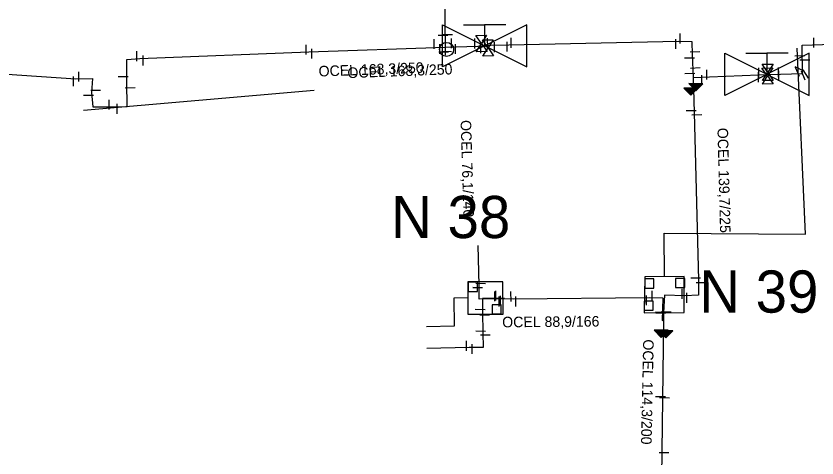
# Model space of a CAD drawing. Extents: x -642943 to -623314, y -1138561 to -1113539.
# Drawn here: x -641799.7 to -641742.7, y -1115261.5 to -1115230.1 of the extents above; entities that cross this region are included whole.
import ezdxf

# ---------------------------------------------------------------- set-up
doc = ezdxf.new("R2010")
doc.units = 0
for name, color, linetype in [('horkovod armatury', 7, 'Continuous'), ('horkovod dimenze', 7, 'Continuous'), ('horkovod předisol', 7, 'Continuous'), ('horkovod sváry', 7, 'Continuous'), ('horkovod trasa', 7, 'Continuous'), ('horkovod zrušený', 7, 'Continuous'), ('horkovod číslo šachty', 7, 'Continuous'), ('horkovod šachty', 7, 'Continuous')]:
    doc.layers.add(name, color=color, linetype=linetype)

# ---------------------------------------------------------------- blocks, each defined once
blk = doc.blocks.new('SPH')
at = {"layer": 'horkovod sváry'}
blk.add_line((0, -0.035), (0, 0.035), dxfattribs=at)
blk = doc.blocks.new('SPH_1')
at = {"layer": 'horkovod sváry'}
blk.add_line((0.0001, -0.035), (-0.0001, 0.035), dxfattribs=at)
blk = doc.blocks.new('SPH_2')
at = {"layer": 'horkovod sváry'}
blk.add_line((-0.0001, -0.0349), (0.0001, 0.0349), dxfattribs=at)
blk = doc.blocks.new('POINT_DISPLAY')
blk.add_line((0, 0), (0, 0))
blk = doc.blocks.new('SH')
at = {"layer": 'horkovod armatury'}
for p, q in [((-0.0568, -0.0385), (-0.0564, 0.0379)), ((-0.0564, 0.0379), (0, 0)), ((0.0007, -0.0004), (0.0582, 0.0375)), ((0.0582, 0.0375), (0.0581, -0.0389)), ((0.0007, -0.0004), (-0.0568, -0.0385)), ((0.0581, -0.0389), (0.0007, -0.0004))]:
    blk.add_line(p, q, dxfattribs=at)
blk = doc.blocks.new('6.46')
at = {"layer": 'horkovod armatury'}
for p, q in [((0, 0.0467), (0.0034, 0.0467)), ((0, 0.0397), (0.0105, 0.0397)), ((0, 0.0327), (0.0177, 0.0327)), ((0, 0.0257), (0.0249, 0.0257)), ((0, 0.0187), (0.032, 0.0187)), ((0, 0.0117), (0.0392, 0.0117)), ((0, 0.0047), (0.0463, 0.0047)), ((0, -0.0023), (0.0488, -0.0023)), ((0, -0.0093), (0.0416, -0.0093)), ((0, -0.0163), (0.0345, -0.0163)), ((0, -0.0233), (0.0273, -0.0233)), ((0, -0.0303), (0.0202, -0.0303)), ((0, -0.0373), (0.013, -0.0373)), ((0, -0.0443), (0.0058, -0.0443))]:
    blk.add_line(p, q, dxfattribs=at)
blk.add_lwpolyline([(0, 0.05), (0, -0.05), (0.0512, 0)], close=True, dxfattribs=at)
blk = doc.blocks.new('SCH_01_10')
at = {"layer": 'horkovod armatury'}
for p, q in [((10, 5), (-10, -5)), ((-10, -5), (-10, 5)), ((-10, 5), (10, -5)), ((-5, 5), (0, 5)), ((0, 5), (0, 0)), ((5, 5), (0, 5)), ((10, -5), (10, 5))]:
    blk.add_line(p, q, dxfattribs=at)

msp = doc.modelspace()

# ---------------------------------------------------------------- linework, layer by layer
at = {"layer": 'horkovod předisol'}
msp.add_line((-641753.655, -1115251.788), (-641753.821, -1115263.96), dxfattribs=at)
for points in [[(-641758.697, -1115223.753), (-641762.335, -1115224.239), (-641769.279, -1115224.732), (-641769.182, -1115232.315)], [(-641751.554, -1115234.469), (-641746.89, -1115234.261), (-641743.761, -1115234.175), (-641743.786, -1115232.164), (-641739.432, -1115232.02), (-641702.421, -1115231.343), (-641702.298, -1115235.396), (-641702.102, -1115236.408), (-641701.237, -1115236.398), (-641688.715, -1115235.999), (-641688.871, -1115231.268), (-641683.013, -1115231.141), (-641670.373, -1115230.715)], [(-641769.182, -1115232.315), (-641766.857, -1115232.233), (-641765.941, -1115232.175), (-641764.652, -1115232.13), (-641752.604, -1115231.888), (-641751.641, -1115231.908), (-641751.606, -1115232.847), (-641751.554, -1115234.469)], [(-641807.004, -1115233.78), (-641795.449, -1115234.548), (-641794.27, -1115234.54), (-641794.336, -1115235.525), (-641794.239, -1115236.552), (-641792.768, -1115236.552), (-641791.81, -1115236.529), (-641791.828, -1115234.784), (-641791.823, -1115233.171), (-641790.889, -1115233.104), (-641778.885, -1115232.64), (-641769.182, -1115232.315)], [(-641769.182, -1115232.315), (-641769.175, -1115232.867)], [(-641751.554, -1115234.469), (-641751.522, -1115235.262), (-641751.478, -1115236.959), (-641751.167, -1115248.877), (-641751.154, -1115249.933), (-641752.138, -1115249.977), (-641753.585, -1115249.94), (-641753.646, -1115251.168), (-641753.655, -1115251.788)], [(-641764.977, -1115250.198), (-641766.758, -1115250.223), (-641766.763, -1115249.228), (-641766.838, -1115246.394)], [(-641764.977, -1115250.198), (-641764.977, -1115250.159), (-641766.535, -1115250.179), (-641766.522, -1115251.143), (-641766.493, -1115252.615), (-641766.473, -1115253.646), (-641767.47, -1115253.656), (-641770.481, -1115253.733)], [(-641753.655, -1115251.788), (-641753.727, -1115251.738), (-641753.682, -1115250.15), (-641754.661, -1115250.123), (-641764.343, -1115250.209), (-641764.977, -1115250.198)]]:
    msp.add_lwpolyline(points, dxfattribs=at)
at = {"layer": 'horkovod trasa'}
msp.add_line((-641753.655, -1115251.788), (-641753.821, -1115263.96), dxfattribs=at)
for points in [[(-641758.697, -1115223.753), (-641762.335, -1115224.239), (-641769.279, -1115224.732), (-641769.182, -1115232.315)], [(-641751.554, -1115234.469), (-641746.89, -1115234.261), (-641743.761, -1115234.175), (-641743.786, -1115232.164), (-641739.432, -1115232.02), (-641702.421, -1115231.343), (-641702.298, -1115235.396), (-641702.102, -1115236.408), (-641701.237, -1115236.398), (-641688.715, -1115235.999), (-641688.871, -1115231.268), (-641683.013, -1115231.141), (-641670.373, -1115230.715)], [(-641769.182, -1115232.315), (-641766.857, -1115232.233), (-641765.941, -1115232.175), (-641764.652, -1115232.13), (-641752.604, -1115231.888), (-641751.641, -1115231.908), (-641751.606, -1115232.847), (-641751.554, -1115234.469)], [(-641807.004, -1115233.78), (-641795.449, -1115234.548), (-641794.27, -1115234.54), (-641794.336, -1115235.525), (-641794.239, -1115236.552), (-641792.768, -1115236.552), (-641791.81, -1115236.529), (-641791.828, -1115234.784), (-641791.823, -1115233.171), (-641790.889, -1115233.104), (-641778.885, -1115232.64), (-641769.182, -1115232.315)], [(-641769.182, -1115232.315), (-641769.175, -1115232.867)], [(-641751.554, -1115234.469), (-641751.522, -1115235.262), (-641751.478, -1115236.959), (-641751.167, -1115248.877), (-641751.154, -1115249.933), (-641752.138, -1115249.977), (-641753.585, -1115249.94), (-641753.646, -1115251.168), (-641753.655, -1115251.788)], [(-641764.977, -1115250.198), (-641766.758, -1115250.223), (-641766.763, -1115249.228), (-641766.838, -1115246.394)], [(-641764.977, -1115250.198), (-641764.977, -1115250.159), (-641766.535, -1115250.179), (-641766.522, -1115251.143), (-641766.493, -1115252.615), (-641766.473, -1115253.646), (-641767.47, -1115253.656), (-641770.481, -1115253.733)], [(-641753.655, -1115251.788), (-641753.727, -1115251.738), (-641753.682, -1115250.15), (-641754.661, -1115250.123), (-641764.343, -1115250.209), (-641764.977, -1115250.198)]]:
    msp.add_lwpolyline(points, dxfattribs=at)
at = {"layer": 'horkovod zrušený'}
for p, q in [((-641743.544, -1115245.588), (-641744.154, -1115232.385)), ((-641778.508, -1115235.381), (-641794.902, -1115236.798)), ((-641753.582, -1115248.63), (-641753.597, -1115245.516)), ((-641753.597, -1115245.516), (-641743.544, -1115245.588)), ((-641767.566, -1115250.135), (-641768.57, -1115250.139)), ((-641768.57, -1115250.139), (-641768.553, -1115252.135)), ((-641768.553, -1115252.135), (-641770.508, -1115252.187))]:
    msp.add_line(p, q, dxfattribs=at)
at = {"layer": 'horkovod šachty'}
for p, q in [((-641767.539, -1115249.02), (-641767.539, -1115249.67)), ((-641766.889, -1115249.02), (-641767.539, -1115249.02)), ((-641766.889, -1115249.67), (-641766.889, -1115249.02)), ((-641754.989, -1115248.78), (-641754.989, -1115249.43)), ((-641754.339, -1115248.78), (-641754.989, -1115248.78)), ((-641754.339, -1115249.43), (-641754.339, -1115248.78)), ((-641752.799, -1115248.75), (-641752.799, -1115249.4)), ((-641752.149, -1115248.75), (-641752.799, -1115248.75)), ((-641752.149, -1115249.4), (-641752.149, -1115248.75)), ((-641767.539, -1115249.67), (-641766.889, -1115249.67)), ((-641754.989, -1115249.43), (-641754.339, -1115249.43)), ((-641752.799, -1115249.4), (-641752.149, -1115249.4)), ((-641755.029, -1115250.36), (-641755.029, -1115251.01)), ((-641754.379, -1115250.36), (-641755.029, -1115250.36)), ((-641754.379, -1115251.01), (-641754.379, -1115250.36)), ((-641765.839, -1115250.62), (-641765.839, -1115251.27)), ((-641765.189, -1115250.62), (-641765.839, -1115250.62)), ((-641765.189, -1115251.27), (-641765.189, -1115250.62)), ((-641765.839, -1115251.27), (-641765.189, -1115251.27)), ((-641755.029, -1115251.01), (-641754.379, -1115251.01))]:
    msp.add_line(p, q, dxfattribs=at)
for points in [[(-641752.179, -1115251.169), (-641752.184, -1115248.619), (-641754.984, -1115248.638), (-641755.018, -1115251.188), (-641752.179, -1115251.169)], [(-641765.066, -1115251.279), (-641765.072, -1115248.979), (-641767.572, -1115248.985), (-641767.566, -1115251.285), (-641765.066, -1115251.279)]]:
    msp.add_lwpolyline(points, dxfattribs=at)
msp.add_circle((-641769.083, -1115232.463), 0.5, dxfattribs=at)

# ---------------------------------------------------------------- block references
at = {"layer": 'horkovod armatury', "xscale": 0.2999795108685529, "yscale": 0.2999795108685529}
for p in [(-641766.374, -1115232.213), (-641746.297, -1115234.236)]:
    msp.add_blockref('SCH_01_10', p, dxfattribs=at)
at = {"layer": 'horkovod armatury'}
for name, p, xscale, yscale, rotation in [('SH', (-641766.598, -1115232.038), 9.999984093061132, 9.99998409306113, -88.00122409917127), ('SH', (-641766.128, -1115232.348), 9.999988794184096, 9.999988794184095, -89.04612800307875), ('SH', (-641746.248, -1115234.348), 9.999994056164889, 9.999994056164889, -87.88081933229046), ('SH', (-641746.238, -1115234.088), 10.000020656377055, 10.000020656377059, -89.52294863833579), ('6.46', (-641751.36, -1115234.9), 9.999978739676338, 9.99997873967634, -90.41168409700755), ('6.46', (-641751.71, -1115235.21), 10, 10, -90.00000000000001), ('6.46', (-641753.82, -1115252.42), 10.000008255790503, 10.000008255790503, -90.58457879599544), ('6.46', (-641753.48, -1115252.46), 10.000008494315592, 10.00000849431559, -91.00723883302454)]:
    msp.add_blockref(name, p, dxfattribs=dict(at, xscale=xscale, yscale=yscale, rotation=rotation))
at = {"layer": 'horkovod sváry'}
for name, p, xscale, yscale, rotation in [('SPH_2', (-641769.34, -1115231.472), 10.000011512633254, 10.000011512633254, 90.92932050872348), ('SPH_2', (-641769.01, -1115231.432), 10.000016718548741, 10.000016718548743, 89.79616110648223), ('SPH_2', (-641769.291, -1115232.64), 9.999997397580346, 9.999997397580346, -91.19804079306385), ('SPH', (-641769.288, -1115232.64), 9.999997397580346, 9.999997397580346, -91.19804079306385), ('SPH_2', (-641769.288, -1115232.64), 9.999997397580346, 9.999997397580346, -91.19804079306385), ('SPH', (-641769.078, -1115232.6), 9.999993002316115, 9.999993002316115, -91.31839937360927), ('SPH', (-641751.42, -1115232.63), 10.000014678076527, 10.000014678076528, -88.46248895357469), ('SPH', (-641751.8, -1115233.07), 9.99998074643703, 9.999980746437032, -89.28787850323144), ('SPH_2', (-641743.96, -1115232.931), 9.999986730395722, 9.99998673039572, 91.14280189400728), ('SPH_2', (-641743.6, -1115233.201), 10.000019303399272, 10.00001930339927, -89.67689839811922), ('SPH_1', (-641751.39, -1115233.77), 9.999996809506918, 9.999996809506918, -86.47221275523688), ('SPH_1', (-641743.99, -1115233.86), 9.99999407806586, 9.99999407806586, 62.764839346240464), ('SPH', (-641744.12, -1115234.07), 9.999997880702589, 9.999997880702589, 25.2680652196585), ('SPH', (-641792.08, -1115234.39), 9.999998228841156, 9.999998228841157, -90.78122855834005), ('SPH_1', (-641751.78, -1115234.16), 9.999983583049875, 9.999983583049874, -88.24574883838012), ('SPH_1', (-641743.7, -1115234.33), 10.000006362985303, 10.000006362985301, 21.91080350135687), ('SPH', (-641743.54, -1115234.21), 10.00000426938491, 10.00000426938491, 32.95191423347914), ('SPH_1', (-641794.04, -1115235.37), 10.000001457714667, 10.000001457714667, -90.39220594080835), ('SPH_1', (-641791.59, -1115235.18), 10.000007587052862, 10.000007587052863, -89.05573607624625), ('SPH_1', (-641794.55, -1115235.73), 9.999997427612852, 9.999997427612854, 89.83004510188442), ('SPH', (-641751.69, -1115236.8), 10.000021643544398, 10.0000216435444, -90.59204892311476), ('SPH', (-641751.28, -1115237.1), 10.000021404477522, 10.000021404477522, -89.1005662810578), ('SPH_1', (-641751.37, -1115248.7), 10.000019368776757, 10.000019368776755, -91.15213818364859), ('SPH_1', (-641766.66, -1115249.09), 10.000000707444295, 10.000000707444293, -91.38805381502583), ('SPH_1', (-641750.98, -1115249.03), 9.999985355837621, 9.999985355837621, -90.73533506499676), ('SPH', (-641766.87, -1115249.39), 10.00000374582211, 10.000003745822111, -91.42141399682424), ('SPH_1', (-641766.69, -1115250.94), 9.999982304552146, 9.999982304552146, -91.66456492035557), ('SPH_1', (-641766.37, -1115251.33), 9.999991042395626, 9.999991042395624, -88.7173614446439), ('SPH_1', (-641753.88, -1115251.13), 9.99998003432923, 9.99998003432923, -91.46892381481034), ('SPH_1', (-641753.84, -1115251.19), 9.99999350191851, 9.999993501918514, -91.11771657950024), ('SPH', (-641753.48, -1115251.12), 9.999979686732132, 9.999979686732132, -91.09983882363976), ('SPH', (-641753.46, -1115251.11), 9.999987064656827, 9.999987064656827, -91.76359312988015), ('SPH_1', (-641766.66, -1115252.48), 10.000015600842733, 10.000015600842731, -91.02458312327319), ('SPH_1', (-641766.33, -1115252.75), 10.000000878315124, 10.000000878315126, -89.23744967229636), ('SPH_1', (-641753.87, -1115257.14), 10.000006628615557, 10.000006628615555, -91.45397399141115), ('SPH_1', (-641753.58, -1115257.22), 9.999979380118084, 9.999979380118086, -92.48259935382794), ('SPH_1', (-641753.62, -1115261.11), 9.999978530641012, 9.999978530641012, -90.21691321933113)]:
    msp.add_blockref(name, p, dxfattribs=dict(at, xscale=xscale, yscale=yscale, rotation=rotation))
at = {"layer": 'horkovod sváry', "xscale": 10, "yscale": 10}
for name, p in [('SPH_1', (-641752.47, -1115231.69)), ('SPH_1', (-641779.06, -1115232.48)), ('SPH_2', (-641769.97, -1115232.082)), ('SPH_2', (-641769.56, -1115232.442)), ('SPH_2', (-641768.74, -1115232.032)), ('SPH_2', (-641768.44, -1115232.432)), ('SPH_1', (-641767.08, -1115232.04)), ('SPH_1', (-641766.65, -1115232.39)), ('SPH_1', (-641766.16, -1115232.01)), ('SPH_1', (-641765.67, -1115232.31)), ('SPH_1', (-641764.78, -1115232.27)), ('SPH_1', (-641764.48, -1115232)), ('SPH_1', (-641752.77, -1115232.08)), ('SPH_2', (-641742.96, -1115231.981)), ('SPH_1', (-641791.12, -1115232.95)), ('SPH_1', (-641778.67, -1115232.77)), ('SPH_1', (-641790.66, -1115233.25)), ('SPH_1', (-641746.87, -1115234.12)), ('SPH_1', (-641745.48, -1115234.1)), ('SPH_1', (-641795.62, -1115234.73)), ('SPH_1', (-641795.23, -1115234.4)), ('SPH_1', (-641750.93, -1115234.65)), ('SPH_1', (-641750.57, -1115234.26)), ('SPH_1', (-641746.9, -1115234.44)), ('SPH_1', (-641745.45, -1115234.34)), ('SPH_1', (-641793.07, -1115236.39)), ('SPH_1', (-641792.5, -1115236.69)), ('SPH_1', (-641765.64, -1115250.02)), ('SPH_1', (-641765.59, -1115249.97)), ('SPH_1', (-641764.5, -1115250.03)), ('SPH_1', (-641754.46, -1115249.97)), ('SPH_1', (-641752.33, -1115249.84)), ('SPH_1', (-641751.99, -1115250.12)), ('SPH_1', (-641765.34, -1115250.38)), ('SPH_1', (-641765.24, -1115250.32)), ('SPH_1', (-641764.16, -1115250.38)), ('SPH_1', (-641754.86, -1115250.3)), ('SPH_1', (-641767.67, -1115253.54)), ('SPH_1', (-641767.26, -1115253.76))]:
    msp.add_blockref(name, p, dxfattribs=at)
at = {"layer": 'horkovod šachty'}
for p in [(-641754.659, -1115249.1), (-641752.469, -1115249.07), (-641767.209, -1115249.34), (-641765.509, -1115250.94), (-641754.699, -1115250.68)]:
    msp.add_blockref('POINT_DISPLAY', p, dxfattribs=at)

# ---------------------------------------------------------------- texts
at = {"layer": 'horkovod dimenze'}
for s, height, rotation, p in [('OCEL 168,3/250', 0.74999, 2.1034, (-641778.17, -1115234.397)), ('OCEL 168,3/250', 0.74999, 2.1034, (-641776.121, -1115234.509)), ('OCEL 76,1/140', 0.74999, 271.7195, (-641768.088, -1115237.498)), ('OCEL 139,7/225', 0.75, 271.4405, (-641749.819, -1115238.048)), ('OCEL 88,9/166', 0.75, 0.4929, (-641765.123, -1115252.223)), ('OCEL 114,3/200', 0.75, 268.7965, (-641755.097, -1115253.071))]:
    msp.add_text(s, height=height, rotation=rotation, dxfattribs=at).set_placement(p)
at = {"layer": 'horkovod číslo šachty'}
for s, p in [('N 38', (-641773.025, -1115245.877)), ('N 39', (-641751.112, -1115251.177))]:
    msp.add_text(s, height=3, dxfattribs=at).set_placement(p)

doc.saveas('drawing.dxf')
